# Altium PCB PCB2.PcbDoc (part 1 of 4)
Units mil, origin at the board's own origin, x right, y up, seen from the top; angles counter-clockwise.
Board outline 3980.79 x 2126 mil, 6 copper layers (Top Layer, Signal Layer 1, Signal Layer 2, Signal Layer 3, Signal Layer 4, Bottom Layer), stack 61.485 mil thick; 358 components, 190 nets, 1000 pads, 509 vias.
Unrouted connection lines stored in the file: 83.
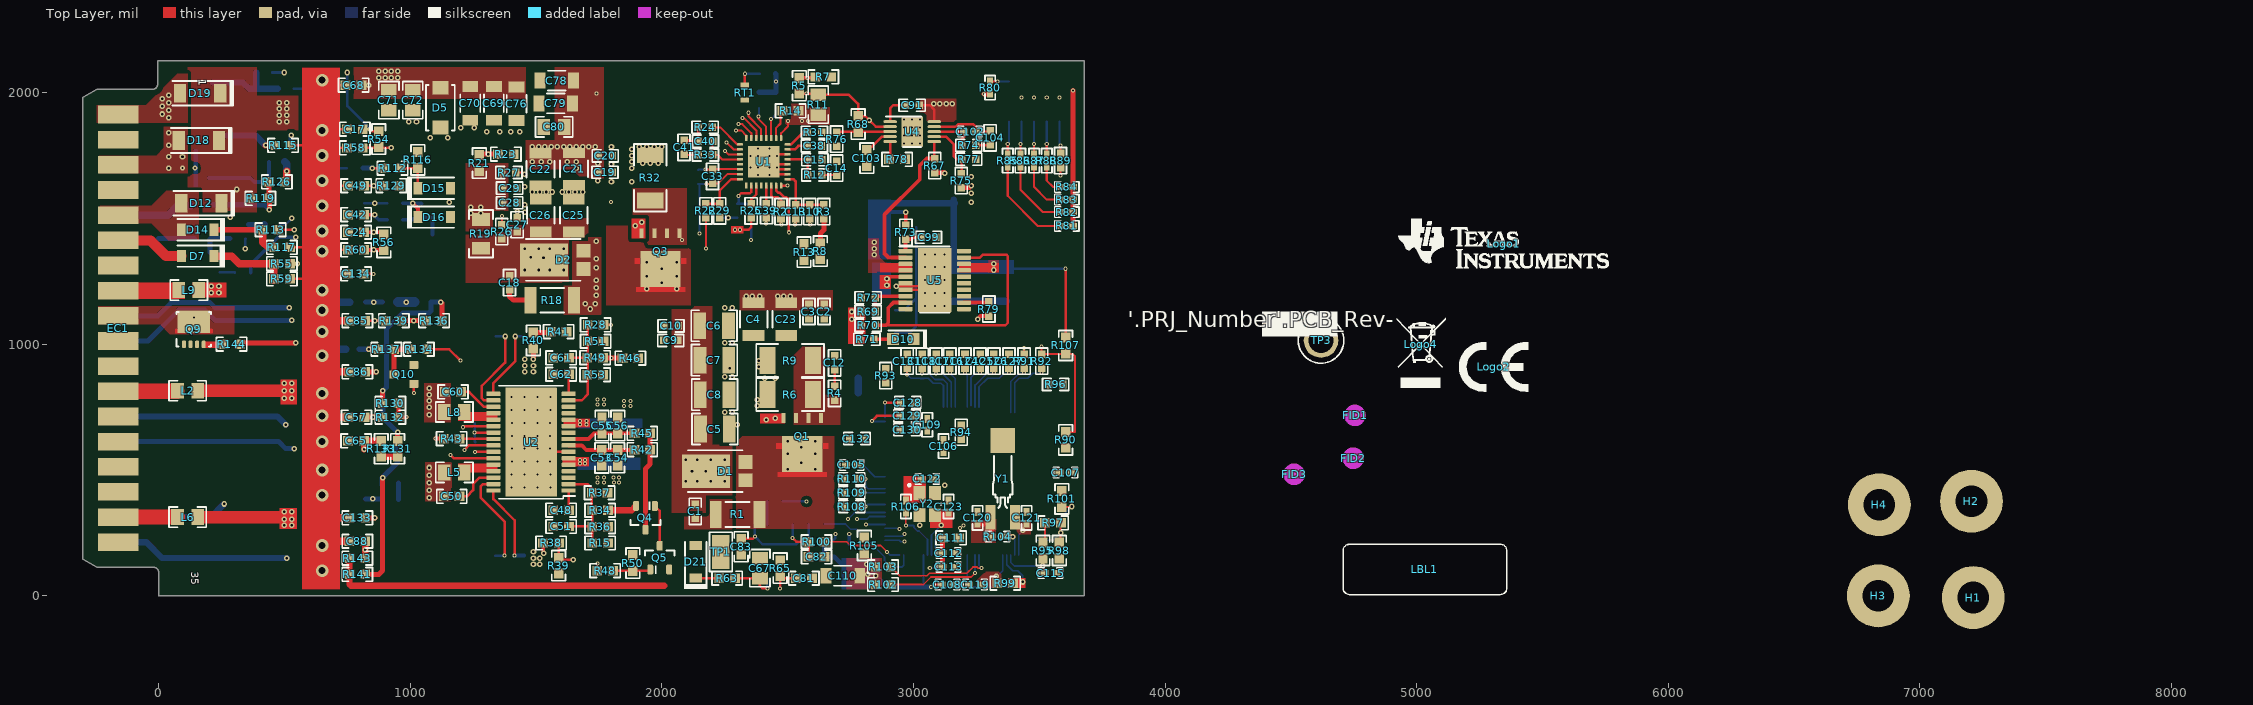
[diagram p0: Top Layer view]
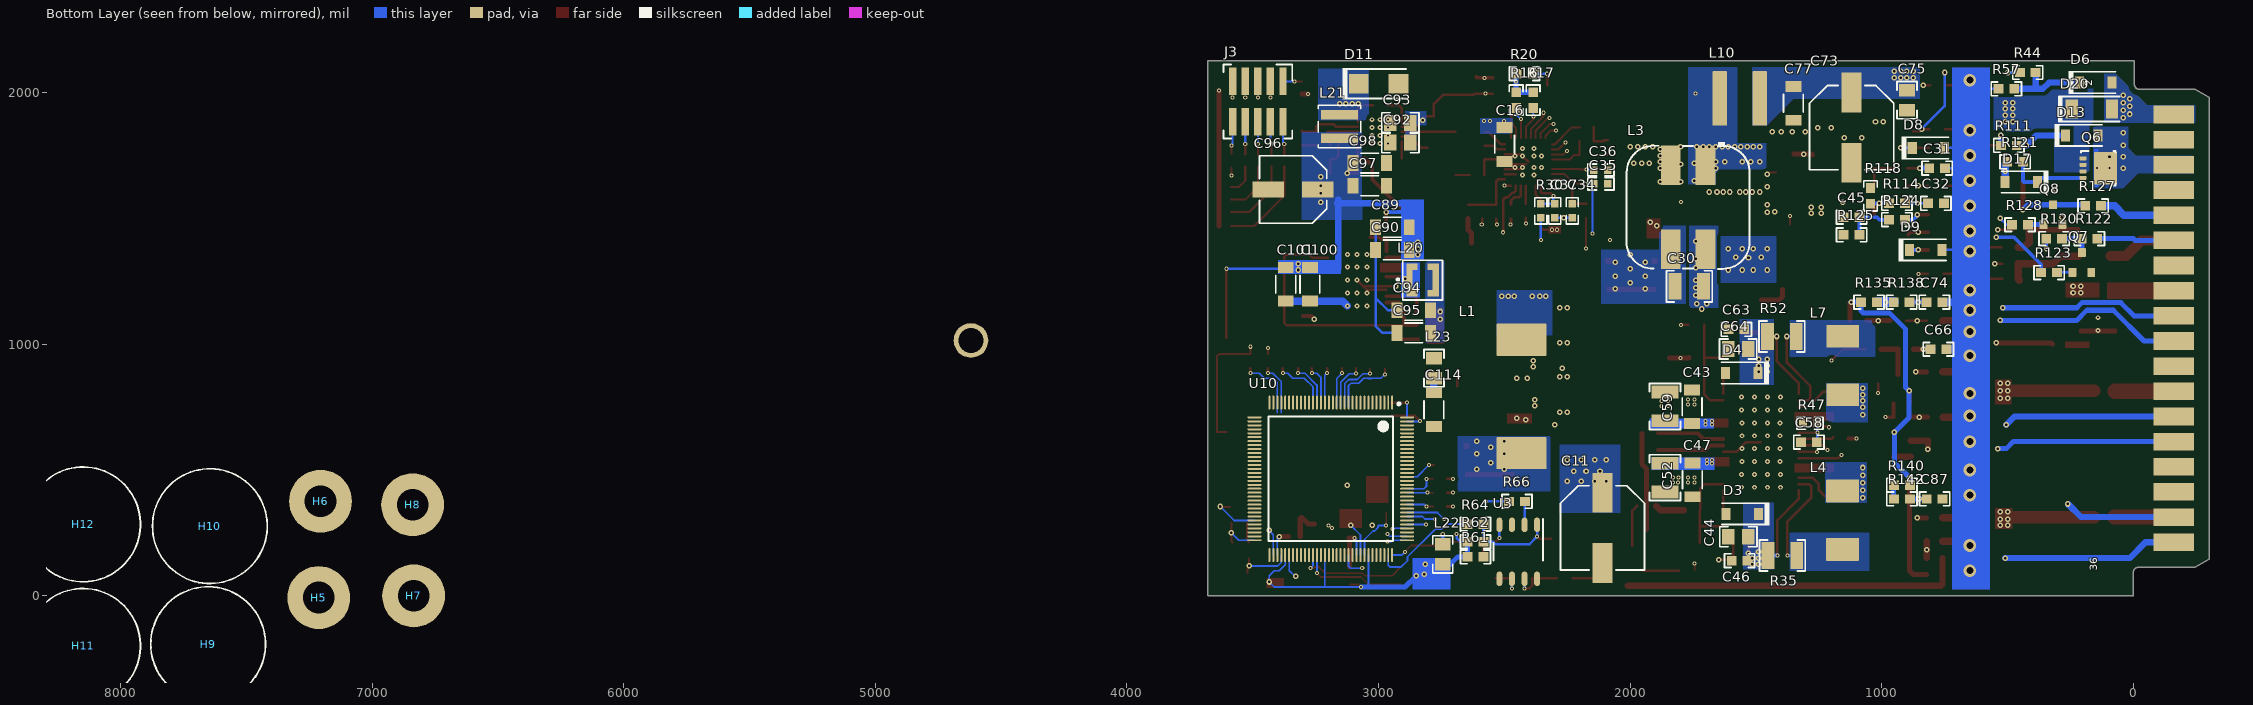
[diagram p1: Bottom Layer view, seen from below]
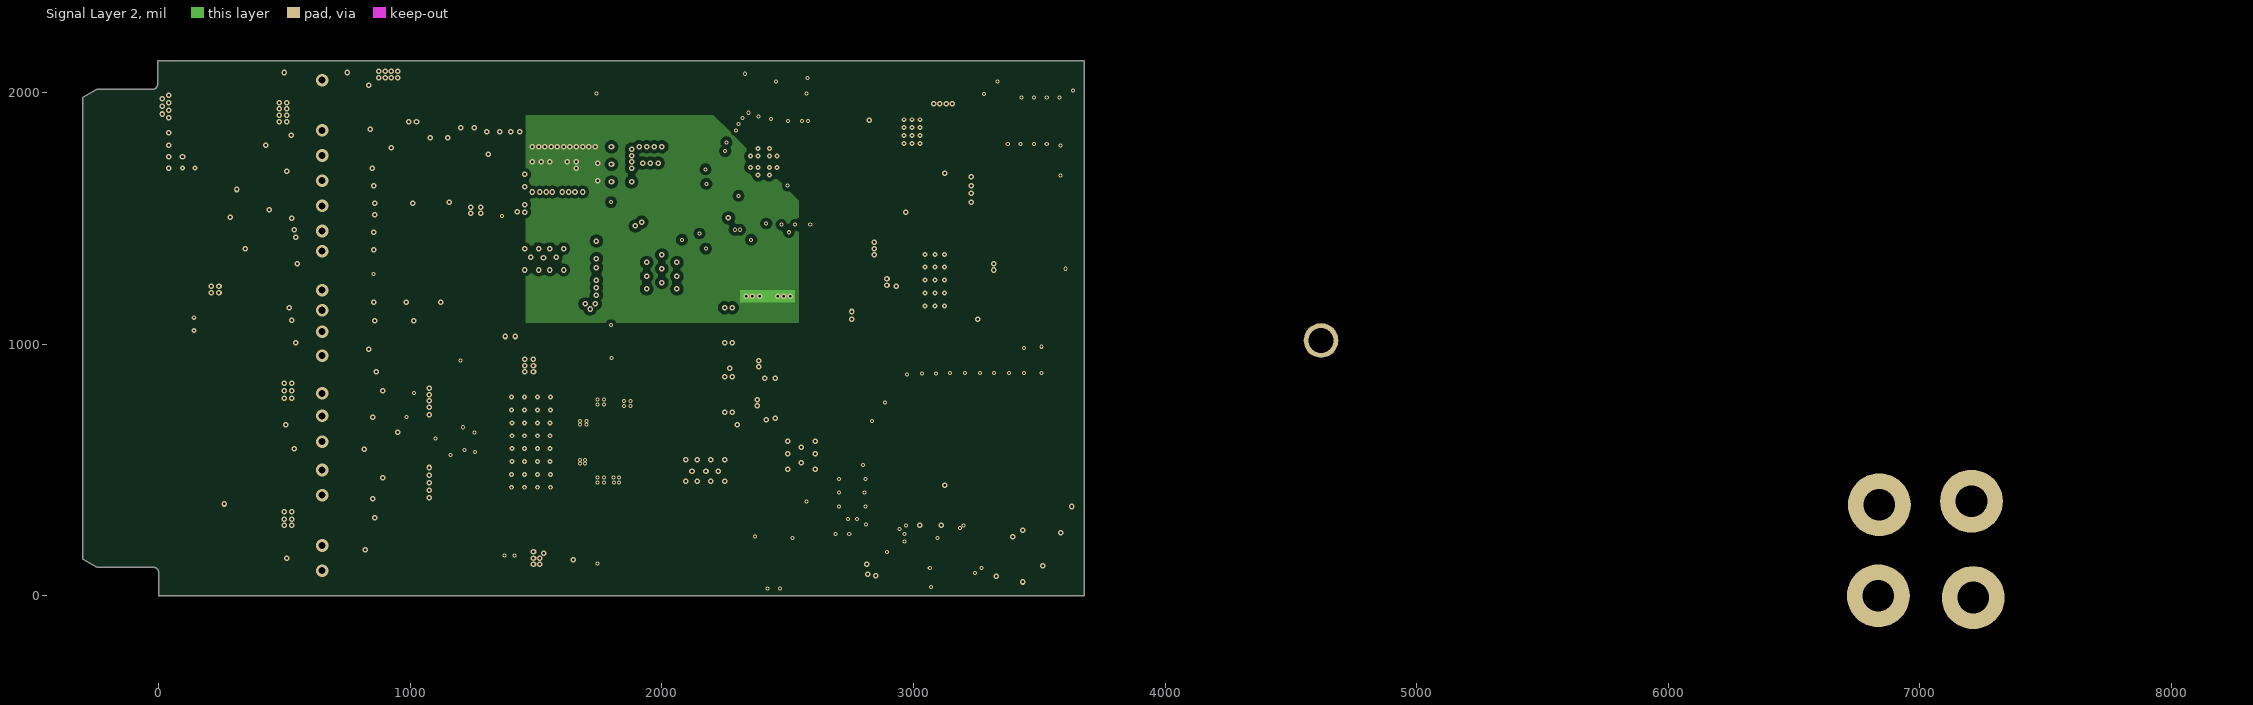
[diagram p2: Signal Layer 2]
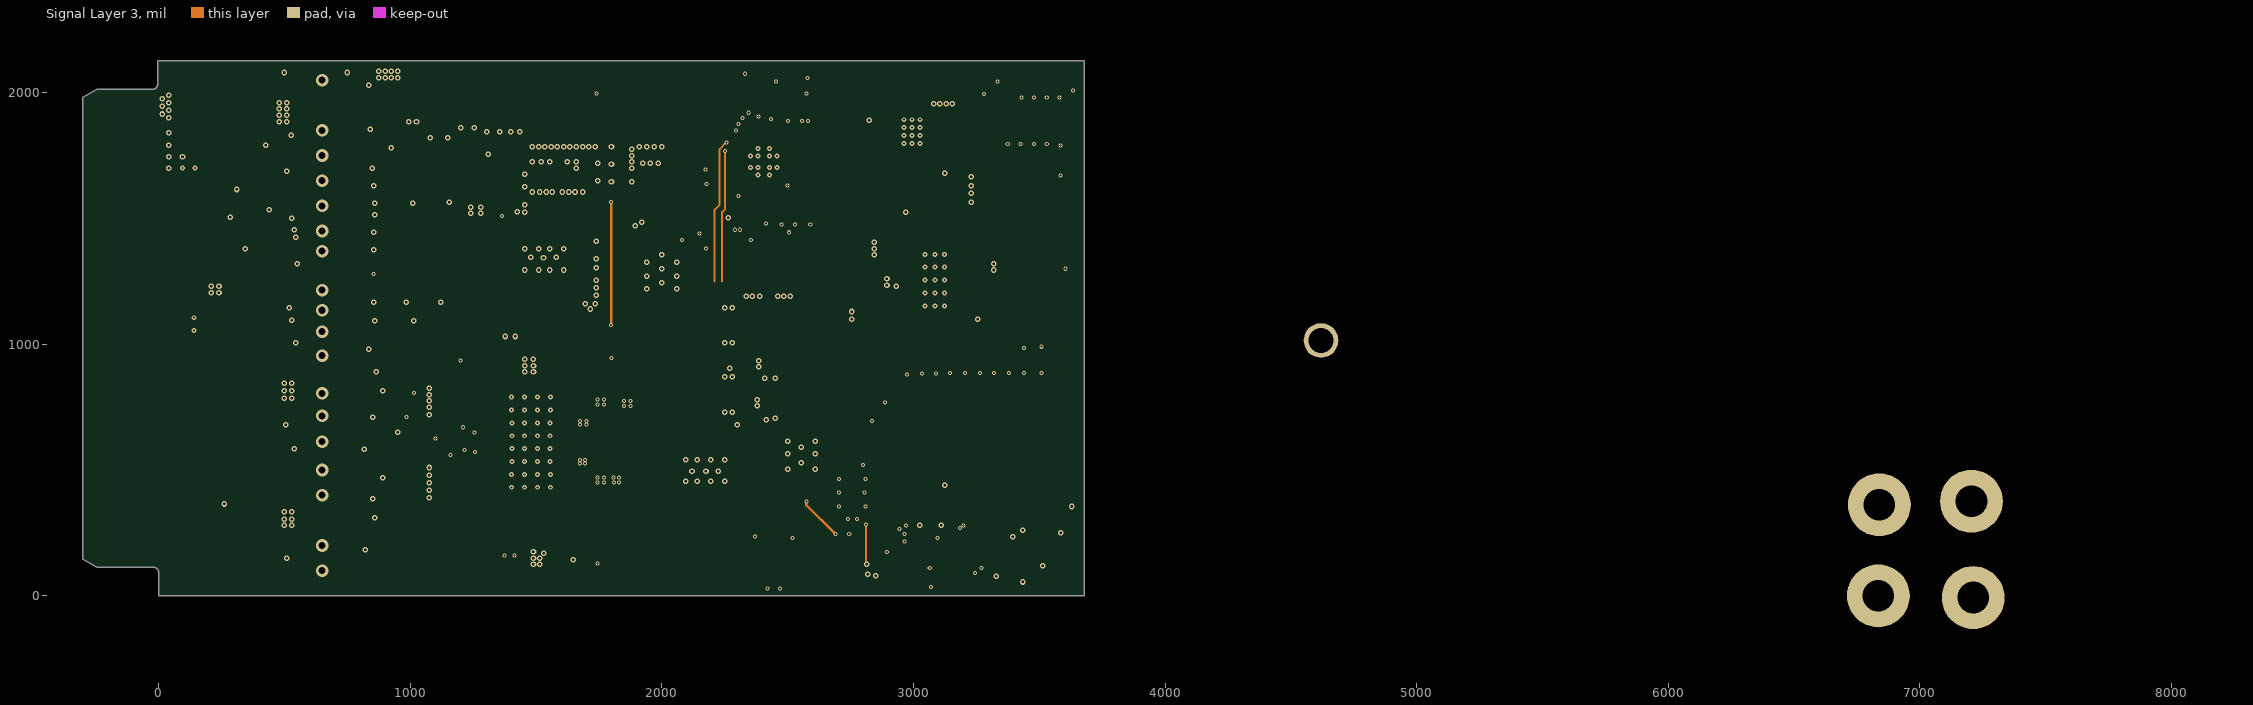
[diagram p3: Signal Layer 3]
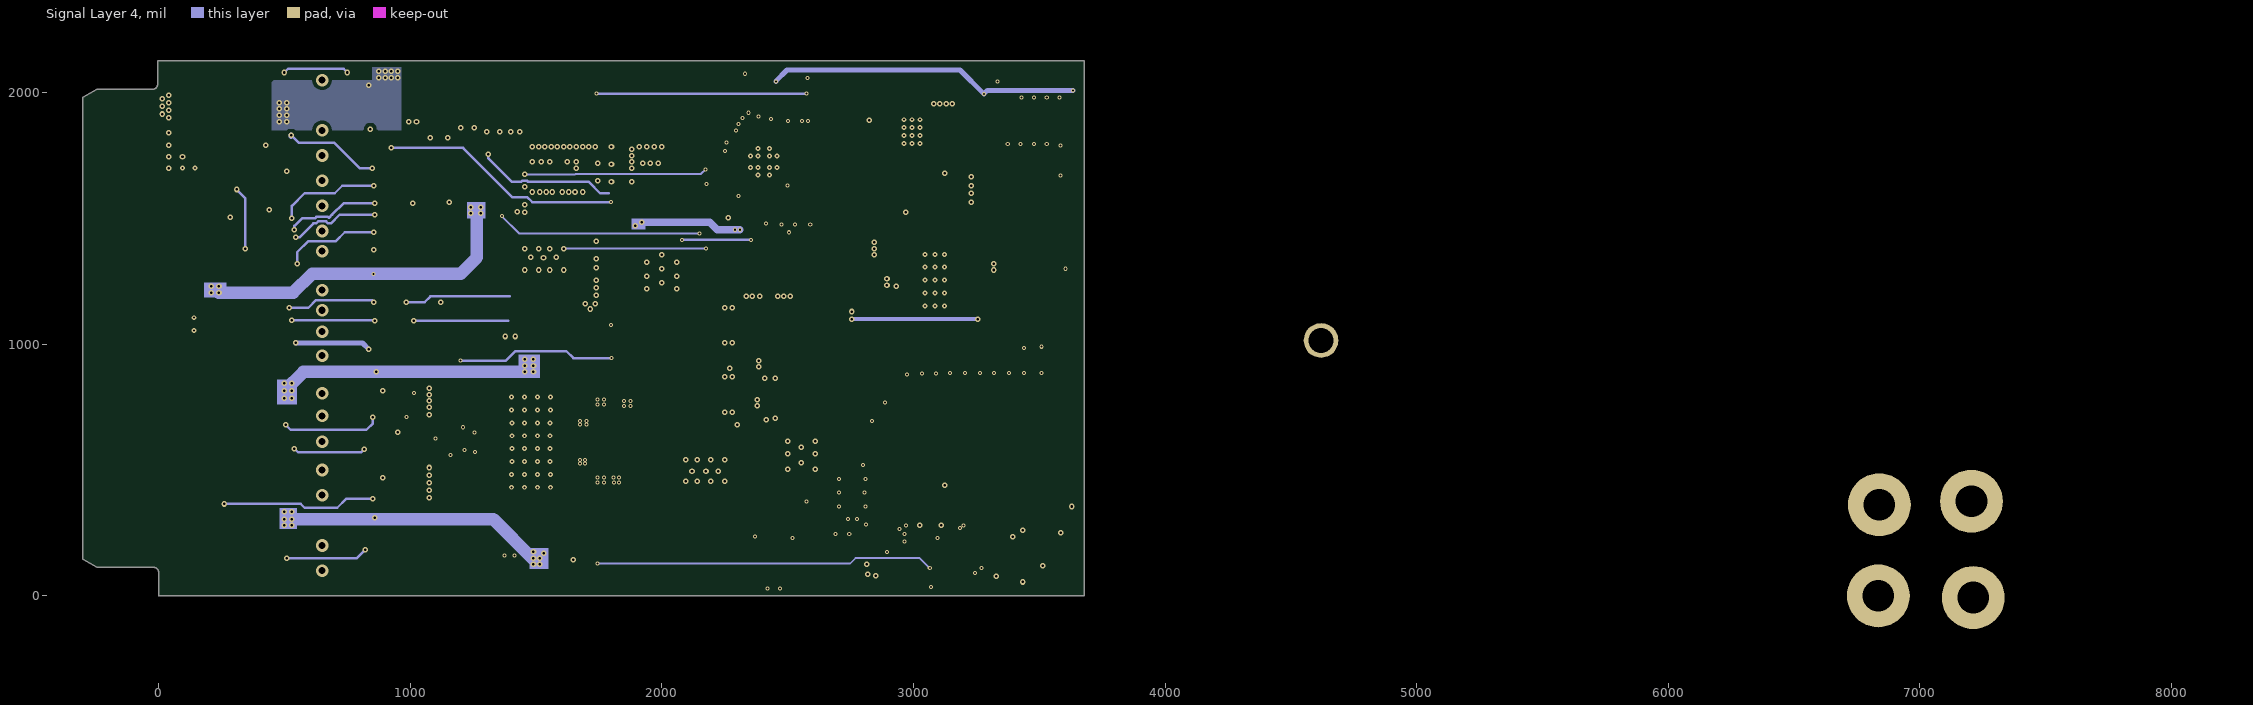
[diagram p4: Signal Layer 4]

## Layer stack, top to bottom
Top Solder: solder mask 0.4, Solder Resist, Dk 3.5
Top Layer: signal copper 1.417
Dielectric 1: core 12, FR-4, Dk 4.2
Signal Layer 1: signal copper 1.417
Dielectric 2: prepreg 8.5, FR-4, Dk 4.2
Signal Layer 2: signal copper 1.4
Dielectric 3: core 12, FR-4, Dk 4.2
Signal Layer 3: signal copper 1.417
Dielectric 4: prepreg 8.5, FR-4, Dk 4.2
Signal Layer 4: signal copper 1.417
Dielectric 5: core 12, Dk 4.2
Bottom Layer: signal copper 1.417
Bottom Solder: solder mask 0.4, Solder Resist, Dk 3.5

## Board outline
-300.79,144.88 -300.79,1981.17 -245.67,2012.99 -23.62,2012.99 ccw(c-23.62,2032.68) -3.94,2032.68 -3.94,2125.98 -3.93,2125.99 3680,2125.99 3680,-0.01 0.01,-0.01 0,0 0,93.31 ccw(c-19.69,93.31) -19.69,112.99 -245.67,112.99

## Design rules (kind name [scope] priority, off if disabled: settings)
AcuteAngle [All] p1: minimum=4.50000000000000E+0001 checktracksonly=FALSE
AssemblyTestPointUsage [All] p1: valid=2
BoardOutlineClearance BoardOutlineClearance_MountingHoles [OnCopper and InComponentClass('Mounting Holes')] p1: gap=40 ignorepadtopadclearanceinfootprint=FALSE
BoardOutlineClearance BoardOutlineClearance_Poly [OnCopper and IsPoly] p2: gap=25 ignorepadtopadclearanceinfootprint=FALSE
BoardOutlineClearance [OnCopper and Not InComponentClass('Logo') and not InComponentClass('FiducialMark') and not InRegion(1000,500,4000,800) and not InPoly] p3: gap=25 ignorepadtopadclearanceinfootprint=FALSE
Clearance Clearance_Keepouts [((IsTrack Or IsArc) And Not InPoly) And IsFree and IsKeepOut vs ((IsTrack Or IsArc) And Not InPoly) And IsFree and IsKeepOut] p1: gap=0 ignorepadtopadclearanceinfootprint=FALSE
Clearance Clearance_Poly [InPolygon] p2: gap=15 ignorepadtopadclearanceinfootprint=FALSE except(0: Arc-Hole Track-Hole SMDPad-Hole THPad-Hole Via-Hole Fill-Hole Poly-Hole Region-Hole Text-Hole)
Clearance Clearance_FiducialMark [IsKeepOut and InComponentClass('FiducialMark') vs IsPad and InComponentClass('FiducialMark')] p3: gap=0 ignorepadtopadclearanceinfootprint=FALSE
Clearance [All] p4: gap=7.87 ignorepadtopadclearanceinfootprint=FALSE except(0: Arc-Hole Track-Hole SMDPad-Hole THPad-Hole Via-Hole Fill-Hole Poly-Hole Region-Hole Text-Hole)
ComponentClearance ComponentClearance_MountingHoles_FiducialMarks [InComponentClass('Mounting Holes') vs InComponentClass('FiducialMark')] p1: gap=50 collisioncheckmode=3 verticalgap=10 showdistances=FALSE
ComponentClearance ComponentClearance_Shunt [InComponentClass('Header') vs InComponentClass('Shunt')] p2: gap=0 collisioncheckmode=3 verticalgap=0 showdistances=FALSE
ComponentClearance ComponentClearance_Logo [InComponentClass('Logo')] p3: gap=50 collisioncheckmode=3 verticalgap=10 showdistances=FALSE
ComponentClearance ComponentClearance_ScrewToNut [(HasFootprint('NY PMS 440 0025 PH')) vs (HasFootprint('Keystone_1902C'))] p4: gap=5 collisioncheckmode=3 verticalgap=10 showdistances=FALSE
ComponentClearance ComponentClearance_MountingHoles [InComponentClass('Mounting Holes')] p5: gap=100 collisioncheckmode=3 verticalgap=100000 showdistances=FALSE
ComponentClearance ComponentClearance_SmallPassives [HasFootprint('0201*') or HasFootprint('0402*') or HasFootprint('0508') or HasFootprint('0603*') or HasFootprint('0612') or HasFootprint('0805*') or HasFootprint('0815*') or HasFootprint('0830*') or HasFootprint('1206*') or HasFootprint('1210*') or HasFootprint('1808*') or HasFootprint('1812*') or HasFootprint('1825*') or HasFootprint('2010*') or HasFootprint('2220*') or HasFootprint('2225*') or HasFootprint('2512*') or HasFootprint('2728*') or HasFootprint('3518*') vs HasFootprint('0201*') or HasFootprint('0402*') or HasFootprint('0508') or HasFootprint('0603*') or HasFootprint('0612') or HasFootprint('0805*') or HasFootprint('0815*') or HasFootprint('0830*') or HasFootprint('1206*') or HasFootprint('1210*') or HasFootprint('1808*') or HasFootprint('1812*') or HasFootprint('1825*') or HasFootprint('2010*') or HasFootprint('2220*') or HasFootprint('2225*') or HasFootprint('2512*') or HasFootprint('2728*') or HasFootprint('3518*')] p6: gap=14.96 collisioncheckmode=3 verticalgap=10 showdistances=FALSE
ComponentClearance ComponentClearance_THtoSMT [IsThruComponent vs IsSMTComponent] p7: gap=40 collisioncheckmode=3 verticalgap=30 showdistances=FALSE
ComponentClearance ComponentClearance_THtoTH [IsThruComponent vs IsThruComponent] p8: gap=30 collisioncheckmode=3 verticalgap=30 showdistances=FALSE
ComponentClearance [All] p9: gap=20 collisioncheckmode=3 verticalgap=10 showdistances=FALSE
DiffPairsRouting [All] p1: maxlimit=100 minlimit=10 mostfreqgap=10 toplayer_minwidth=15 toplayer_maxwidth=15 toplayer_prefwidth=15 midlayer1_minwidth=15 midlayer1_maxwidth=15 midlayer1_prefwidth=15 midlayer2_minwidth=15 midlayer2_maxwidth=15 midlayer2_prefwidth=15 midlayer3_minwidth=15 midlayer3_maxwidth=15 midlayer3_prefwidth=15 midlayer4_minwidth=15 midlayer4_maxwidth=15 midlayer4_prefwidth=15 bottomlayer_minwidth=15 bottomlayer_maxwidth=15 bottomlayer_prefwidth=15 maxuncoupledlength=1000
FabricationTestPointUsage TestPointUsage [All] p1: valid=2 allowmultiple=FALSE
FabricationTestpoint Testpoint [All] p1: side=3 testpointundercomponent=TRUE minsize=40 maxsize=100 preferedsize=60 minholesize=0 maxholesize=40 preferedholesize=32 testpointgrid=1 allowsidetop=TRUE allowsidebottom=TRUE usegrid=TRUE gridtolerance=0.01
FanoutControl Fanout_LCC [IsLCC] p1: bgadir=Out bgaviamode=Centered fanoutstyle=Auto fanoutdirection=Alternating viagrid=1 // Fanout_LCC (Default Rule)
FanoutControl Fanout_BGA [IsBGA] p2: bgadir=Out bgaviamode=Centered fanoutstyle=Auto fanoutdirection=Alternating viagrid=1 // Fanout_BGA (Default Rule)
FanoutControl Fanout_Default [All] p4: bgadir=Out bgaviamode=Centered fanoutstyle=Auto fanoutdirection=Alternating viagrid=1 // Fanout_Default (Default Rule)
FanoutControl Fanout_Small [(CompPinCount < 5)] p5: bgadir=Out bgaviamode=Centered fanoutstyle=Auto fanoutdirection=OutThenIn viagrid=1 // Fanout_Small (Default Rule)
HoleSize [All] p1: absolutevalues=TRUE maxlimit=251 minlimit=7.87 maxpercent=80.000 minpercent=20.000
MinimumAnnularRing MinimumAnnularRing_ThermalPadVias [IsVia and InAnyComponent] p1: minimumring=5.91
MinimumAnnularRing [All] p2: minimumring=8
MinimumSolderMaskSliver MinimumSolderMaskSliver_Logo [InComponentClass('Logo') vs InComponentClass('Logo')] p1: minsoldermaskwidth=0.7
MinimumSolderMaskSliver [All] p2: minsoldermaskwidth=3.94
PlaneConnect [All] p1: planeconnectstyle=Relief reliefexpansion=10 reliefentries=4 reliefconductorwidth=10 reliefairgap=10
PolygonConnect [All] p1: connectstyle=Direct reliefconductorwidth=10 reliefentries=4 polygonreliefangle="90 Angle" airgapwidth=10
RoutingVias ThermalPadVias [IsVia and InAnyComponent] p1: holewidth=7.87 width=19.68 viastyle="Through Hole" minholewidth=7.87 minwidth=19.68 maxholewidth=12.99 maxwidth=23.62
RoutingVias [All] p2: holewidth=16 width=34 viastyle="Through Hole" minholewidth=7.87 minwidth=26 maxholewidth=40 maxwidth=65
SilkToBoardRegionClearance [Not ((IsComment or IsDesignator) And (Hide <> 'False')) and not InRegion(1000,500,4000,800)] p1:
SilkToSilkClearance SilkToSilkClearance_Pb-FreeLogo [(HasFootprint('Pb-Free_Overlay_Medium') OR HasFootprint('Pb-Free_Overlay_Small')) vs (HasFootprint('Pb-Free_Overlay_Medium') OR HasFootprint('Pb-Free_Overlay_Small'))] p1: silktosilkclearance=0
SilkToSilkClearance [All] p2: silktosilkclearance=4
SilkToSolderMaskClearance SilkToComponentPadClearance [(IsPad or IsFill or IsRegion) and InAnycomponent] p1: minsilkscreentomaskgap=5 clearancetoexposedcopper=TRUE
SilkToSolderMaskClearance "Silk to Solder Mask Opening" [All] p2: minsilkscreentomaskgap=4 clearancetoexposedcopper=FALSE
SolderMaskExpansion [All] p1: expansion=1.97
Width [All] p1: maxlimit=100 minlimit=6 preferedwidth=10 checkconnectedcopper=TRUE
15 further rules are at their usual default settings.

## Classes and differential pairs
component class "Mounting Holes": H1 H2 H3 H4
component class Logo: Logo1
component class EVM_Hardware: FID1 FID2 FID3 H1 H2 H3 H4 H5 H6 H7 H8 H9 H10 H11 H12 LBL1 Logo1 Logo2 Logo3 Logo4 ZZ1 ZZ2 ZZ3 ZZ4
component class FiducialMark: FID1 FID2 FID3
component class AssemblyNote: ZZ1 ZZ2 ZZ3 ZZ4
component class Label: LBL1
component class "BOOST- SEPIC": C1 C2 C3 C4 C5 C6 C7 C8 C9 C10 C11 C12 C13 C14 C15 C16 C18 C19 C20 C21 C22 C23 C25 C26 C27 C28 C29 C30 C33 C34 C35 C36 C37 C38 C39 C40 C41 D1 D2 L1 L3 Q1 Q3 R1 R2 R3 R4 R5 R6 R7 R8 R9 R10 R11 R12 R13 R14 R16 R17 R18 R19 R20 R21 R22 R23 R24 R25 R26 R27 R29 R30 R31 R32 R33 R90 R107 RT1 TP3 U1
component class Buck: C43 C44 C46 C47 C48 C50 C51 C52 C53 C54 C55 C56 C58 C59 C60 C61 C62 C63 C64 D3 D4 L4 L5 L7 L8 Q4 Q5 R15 R28 R34 R35 R36 R37 R38 R39 R40 R41 R42 R43 R45 R46 R47 R48 R49 R50 R51 R52 R53 U2
component class Header: J3
component class TIDA-0x_Battery: C17 C24 C31 C32 C42 C45 C49 C57 C65 C66 C68 C69 C70 C71 C72 C73 C74 C75 C76 C77 C78 C79 C80 C85 C86 C87 C88 C133 C134 C? D5 D6 D7 D8 D9 D12 D13 D14 D15 D16 D17 D18 D19 D20 D? EC1 L2 L6 L9 L10 Q6 Q7 Q8 Q9 Q10 Q? R44 R54 R55 R56 R57 R58 R59 R60 R111 R112 R113 R114 R115 R116 R117 R118 R119 R120 R121 R122 R123 R124 R125 R126 R127 R128 R129 R130 R131 R132 R133 R134 R135 R136 R137 R138 R139 R140 R141 R142 R143 R144 R?
component class TIDA-0x_MSP432E4x: C67 C81 C82 C83 C105 C106 C107 C108 C109 C110 C111 C112 C113 C114 C115 C116 C117 C118 C119 C120 C121 C122 C123 C124 C125 C126 C127 C128 C129 C130 C131 C132 C? D21 J3 L22 L23 R61 R62 R63 R64 R65 R66 R80 R81 R82 R83 R84 R85 R86 R87 R88 R89 R91 R92 R93 R94 R95 R96 R97 R98 R99 R100 R101 R102 R103 R104 R105 R106 R108 R109 R110 TP1 U3 U10 Y1 Y2
component class TIDA-0x_PwrSupplies: C89 C90 C91 C92 C93 C94 C95 C96 C97 C98 C99 C100 C101 C102 C103 C104 D10 D11 L20 L21 R67 R68 R69 R70 R71 R72 R73 R74 R75 R76 R77 R78 R79 U4 U5

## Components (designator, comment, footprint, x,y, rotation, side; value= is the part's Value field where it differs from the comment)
C1 "Capacitor" 0603_HV 2133,335.68 r90 top value=470pF
C2 "Capacitor" 0603_HV 2645,1130 r90 top value=0.01uF
C3 "Capacitor" 0603_HV 2585,1130 r90 top value=0.1uF
C4 "C3225X7R1H106M250AC" 1210_280 2365,1100 r270 top value=10uF
C5 "Capacitor" 1210_220 2210.91,662.68 r0 top value=4.7uF
C6 "Capacitor" 1210_220 2207.91,1073.68 r0 top value=4.7uF
C7 "Capacitor" 1210_220 2208.91,936.68 r0 top value=4.7uF
C8 "Capacitor" 1210_220 2209.97,799.68 r0 top value=4.7uF
C9 "Capacitor" 0603_HV 2035.61,1014.91 r180 top value=0.1uF
C10 "Capacitor" 0603_HV 2036.61,1072.91 r0 top value=0.01uF
C11 "EEE-FK1K330P" SM_RADIAL_F 2110,270 r270 bottom value=33uF
C12 "Capacitor" 0603_HV 2687,925.68 r270 top value=1000pF
C13 "Capacitor" 0603_HV 2531.76,1527.24 r90 top value=1000pF
C14 "GRM188R71E473KA01D" 0603_HV 2695,1700 r90 top value=0.047uF
C15 "885012006057" 0603_HV 2608.2,1732.94 r180 top value=100pF
C16 "Capacitor" 1206_180 2499.49,1793.9 r270 bottom value=1uF
C17 "GCM188R72A332KA37D" 0603 780,1855 r180 top value=3300pF
C18 "Capacitor" 0603_HV 1395,1245 r90 top value=470pF
C19 "Capacitor" 0603_HV 1774.15,1683.76 r180 top value=0.01uF
C20 "Capacitor" 0603_HV 1775.15,1748.76 r0 top value=0.1uF
C21 "C3225X7R1H106M250AC" 1210_280 1651.15,1696.76 r270 top value=10uF
C22 "C3225X7R1H106M250AC" 1210_280 1518.15,1694.76 r270 top value=10uF
C23 "C3225X7R1H106M250AC" 1210_280 2495,1100 r270 top value=10uF
C24 "GCM188R72A332KA37D" 0603 785,1445 r180 top value=3300pF
C25 "C3225X7R1H106M250AC" 1210_280 1650.15,1511.76 r90 top value=10uF
C26 "C3225X7R1H106M250AC" 1210_280 1519.15,1511.76 r90 top value=10uF
C27 "Capacitor" 0603_HV 1425,1475 r90 top value=0.1uF
C28 "Capacitor" 0603_HV 1395.2,1562.44 r0 top value=0.01uF
C29 "Capacitor" 0603_HV 1395.2,1620.44 r0 top value=0.01uF
C30 "Capacitor" 1210_220 1765,1230 r180 bottom value=4.7uF
C31 "GCM188R72A332KA37D" 0603 780,1700 r180 bottom value=3300pF
C32 "GCM188R72A332KA37D" 0603 785,1560 r180 bottom value=3300pF
C33 "Capacitor" 0603_HV 2201.85,1667.24 r90 top value=0.1uF
C34 "Capacitor" 0603_HV 2230,1530 r90 bottom value=1000pF
C35 "Capacitor" 0603_HV 2116.85,1637.24 r180 bottom value=0.01uF
C36 "Capacitor" 0603_HV 2116.85,1692.24 r180 bottom value=0.01uF
C37 "Capacitor" 0603_HV 2300,1530 r90 bottom value=1000pF
C38 "Capacitor" 0603_HV 2606.52,1787.94 r180 top value=2.2uF
C39 "Capacitor" 0603_HV 2416,1531 r90 top value=2.2uF
C40 "885012006057" 0603_HV 2173.5,1807.24 r180 top value=100pF
C41 "CGA3E3X7S2A104K080AB" 0603_HV 2088.5,1782.24 r90 top value=0.1uF
C42 "GCM188R72A332KA37D" 0603 785,1515 r180 top value=3300pF
C43 "CGA5L3X7S2A225M160AB" 1206_190 1754,751.77 r270 bottom value=2.2uF
C44 "CGA4F3X7S2A224M085AE" 0805_HV 1570,235 r0 bottom value=0.22uF
C45 "GCM188R72A332KA37D" 0603 1120,1505 r0 bottom value=3300pF
C46 "CGA3E3X7S2A104K080AB" 0603 1565,140 r0 bottom value=0.1uF
C47 "CGA5L3X7S2A225M160AB" 1206_190 1753,460.77 r270 bottom value=2.2uF
C48 "GRM188R71C222KA01D" 0603 1600.2,340.59 r180 top value=2200pF
C49 "GCM188R72A332KA37D" 0603 785,1630 r180 top value=3300pF
C50 "CGA3E2X7R1E104K080AA" 0603 1165.2,395.59 r0 top value=0.1uF
C51 "GRM188R72A102KA01D" 0603 1600.2,275.59 r180 top value=1000pF
C52 "CGA6M3X7R2A155K200AB" 1210_220 1862,469.77 r90 bottom value=1.5uF
C53 "GCM188R71C105KA64D" 0603 1761.56,548.59 r90 top value=1uF
C54 "CL10B104KO8WPNC" 0603 1824.37,548.77 r90 top value=0.1uF
C55 "GCM188R71C105KA64D" 0603 1762.37,676.77 r90 top value=1uF
C56 "CL10B104KO8WPNC" 0603 1825.37,676.77 r90 top value=0.1uF
C57 "GCM188R72A332KA37D" 0603 786.5,710 r180 top value=3300pF
C58 "CL10B104KO8WPNC" 0603 1290.2,610.59 r0 bottom value=0.1uF
C59 "CGA6M3X7R2A155K200AB" 1210_220 1862,752.77 r90 bottom value=1.5uF
C60 "CGA3E2X7R1E104K080AA" 0603 1170.2,810.59 r0 top value=0.1uF
C61 "GRM188R72A102KA01D" 0603 1600.2,945.59 r0 top value=1000pF
C62 "GRM188R71C222KA01D" 0603 1600.2,880.59 r180 top value=2200pF
C63 "CGA3E3X7S2A104K080AB" 0603 1578,1058.77 r180 bottom value=0.1uF
C64 "CGA4F3X7S2A224M085AE" 0805_HV 1571,980.77 r0 bottom value=0.22uF
C65 "GCM188R72A332KA37D" 0603 785,616.06 r180 top value=3300pF
C66 "GCM188R72A332KA37D" 0603 775,980 r180 bottom value=3300pF
C67 "C0805C104K5RACAUTO" 0805_HV 2390,110 r270 top value=0.1uF
C68 "GCM188R71H103KA37D" 0603 775,2030 r180 top value=0.01uF
C69 "C3216X7R1H475K160AC" 1206_180 1332.6,1956.99 r270 top value=4.7uF
C70 "C3216X7R1H475K160AC" 1206_180 1238.6,1956.99 r270 top value=4.7uF
C71 "C0805C104K5RACAUTO" 0805_HV 915,1970 r270 top value=0.1uF
C72 "C0805C104K5RACAUTO" 0805_HV 1010,1970 r270 top value=0.1uF
C73 "EEE-FK1H101P" SM_RADIAL_F 1120,1860.67 r270 bottom value=100uF
C74 "GCM188R72A332KA37D" 0603 791,1167.27 r180 bottom value=3300pF
C75 "C0805C104K5RACAUTO" 0805_HV 900,1970 r270 bottom value=0.1uF
C76 "C3216X7R1H475K160AC" 1206_180 1422.6,1955.99 r270 top value=4.7uF
C77 "C3216X7R1H475K160AC" 1206_180 1351.6,1956.99 r270 bottom value=4.7uF
C78 "C3216X7R1H475K160AC" 1206_180 1582.6,2047.99 r180 top value=4.7uF
C79 "C3216X7R1H475K160AC" 1206_180 1578.6,1956.99 r180 top value=4.7uF
C80 "C0805C104K5RACAUTO" 0805_HV 1571.6,1863.99 r180 top value=0.1uF
C81 "GCM1885C2A221JA16D" 0603 2565,70 r180 top value=220pF
C82 "GCM1885C2A150JA16D" 0603 2615,155 r0 top value=15pF
C83 "GCM1885C2A150JA16D" 0603 2315,195 r270 top value=15pF
C85 "GCM188R72A332KA37D" 0603 790,1093.7 r180 top value=3300pF
C86 "GRM188R72A103KA01D" 0603 790,890 r180 top value=0.01uF
C87 "GCM188R72A332KA37D" 0603 790,385 r180 bottom value=3300pF
C88 "GCM188R72A332KA37D" 0603 790,216.85 r180 top value=3300pF
C89 "Capacitor" 1206_180 2945,1465 r0 bottom value=10uF
C90 "Capacitor" 1206_180 2945,1375 r0 bottom value=10uF
C91 "Capacitor" 0603_HV 2995,1950 r0 top value=0.1uF
C92 "CGA4J3X7S2A105K125AB" 0805_HV 2913.61,1801.16 r0 bottom value=1uF
C93 "CGA4J2X7R2A104K125AA" 0805_HV 2913.61,1879.96 r0 bottom value=0.1uF
C94 "Capacitor" 1206_180 2860,1135 r0 bottom value=10uF
C95 "Capacitor" 1206_180 2860,1045 r0 bottom value=10uF
C96 "EEEFP1C101AP" SM_RADIAL_D 3340,1615 r0 bottom value=100uF
C97 "Capacitor" 1206_180 3035,1630 r180 bottom value=10uF
C98 "Capacitor" 1206_180 3035,1720 r180 bottom value=10uF
C99 "Capacitor" 0603_HV 3060,1425 r0 top value=1uF
C100 "Capacitor" 1206_180 3273.21,1238.32 r270 bottom value=10uF
C101 "Capacitor" 1206_180 3369.21,1238.32 r270 bottom value=10uF
C102 "GRM1555C2A5R0CA01D" 0402 3225,1845 r0 top value=5pF
C103 "CGA3E2X7R2A223K080AA" 0603 2815,1740 r270 top value=0.022uF
C104 "Capacitor" 0603_HV 3305,1820 r90 top value=3900pF
C105 "GRM155R71C104KA88D" 0402 2755,520 r180 top value=0.1uF
C106 "GRM155R71C104KA88D" 0402 3120,595 r270 top value=0.1uF
C107 "GRM155R71C104KA88D" 0402 3605,490 r0 top value=0.1uF
C108 "GRM155R71C104KA88D" 0402 3135,45 r0 top value=0.1uF
C109 "GRM155R71C104KA88D" 0402 3055,680 r270 top value=0.1uF
C110 "Capacitor" 1206_180 2720,80 r180 top value=10uF
C111 "GRM188R61C225KE15D" 0603 3150,230 r0 top value=2.2uF
C112 "GRM155R61A105KE15D" 0402 3140,170 r0 top value=1uF
C113 "GRM155R71C104KA88D" 0402 3140,115 r0 top value=0.1uF
C114 "Capacitor" 1206_180 2780,740 r270 bottom value=2.2uF
C115 "GRM155R71C104KA88D" 0402 3545,90 r0 top value=0.1uF
C116 "C0603C331K5RACTU" 0603_HV 3145,933 r90 top value=330pF
C117 "C0603C331K5RACTU" 0603_HV 3090,933 r90 top value=330pF
C118 "C0603C331K5RACTU" 0603_HV 3035,932.45 r90 top value=330pF
C119 "GRM155R71C104KA88D" 0402 3245,45 r180 top value=0.1uF
C120 "GRM1555C1H120JA01D" 0402 3255,310 r90 top value=12pF
C121 "GRM1555C1H120JA01D" 0402 3450,310 r90 top value=12pF
C122 "GRM1555C1H120JA01D" 0402 3055,465 r0 top value=12pF
C123 "GRM1555C1H120JA01D" 0402 3140,355 r90 top value=12pF
C124 "C0603C331K5RACTU" 0603_HV 3205,933 r90 top value=330pF
C125 "C0603C331K5RACTU" 0603_HV 3265,933 r90 top value=330pF
C126 "C0603C331K5RACTU" 0603_HV 3320,933 r90 top value=330pF
C127 "C0603C331K5RACTU" 0603_HV 3380,933 r90 top value=330pF
C128 "C0603C331K5RACTU" 0603_HV 2977.4,768.15 r0 top value=330pF
C129 "C0603C331K5RACTU" 0603_HV 2975,715 r0 top value=330pF
C130 "C0603C331K5RACTU" 0603_HV 2975,660 r0 top value=330pF
C131 "C0603C331K5RACTU" 0603_HV 2975,932.45 r90 top value=330pF
C132 "C0603C331K5RACTU" 0603_HV 2775,625 r180 top value=330pF
C133 "GRM188R72A103KA01D" 0603 790,310 r180 top value=0.01uF
C134 "GRM188R72A103KA01D" 0603 785,1280 r180 top value=0.01uF
D1 "PDS3100Q-13" POWERDI5 2254,495.68 r180 top value=100V
D2 "PDS3100Q-13" POWERDI5 1610,1335 r180 top value=100V
D3 "BAS16D-E3-08" SOD-123 1555,325.77 r0 bottom value=100V
D4 "BAS16D-E3-08" SOD-123 1557,885.77 r0 bottom value=100V
D5 "SZ1SMA28CAT3G" SMA_Bi 1120,1940 r90 top value=28V
D6 "1N4148WQ-7-F" SOD-123 150,2040 r180 bottom value=100V
D7 "1N4148WQ-7-F" SOD-123 155,1350 r180 top value=100V
D8 "MMSZ4683-E3-08" SOD-123 814.43,1780 r180 bottom value=3V
D9 "MMSZ4683-E3-08" SOD-123 825,1375 r180 bottom value=3V
D10 "LED" LG_R971_Green 2960,1020 r0 top value=Green
D11 "DIODE_SCHOTTKY" SMA 3000,2035 r180 bottom value=60V
D12 "FSV530AF" SMAF 170,1560 r180 top value=30V
D13 "1N4148WQ-7-F" SOD-123 205,1830 r180 bottom value=100V
D14 "1N4148WQ-7-F" SOD-123 155,1455 r180 top value=100V
D15 "MMSZ4683-E3-08" SOD-123 1095,1620 r0 top value=3V
D16 "MMSZ4683-E3-08" SOD-123 1095,1505 r0 top value=3V
D17 "MMSZ4697-HE3-08" SOD-123 445,1645 r0 bottom value=10V
D18 "FSV530AF" SMAF 160,1810 r180 top value=30V
D19 "FSV530AF" SMAF 165,1997.5 r180 top value=30V
D20 "FSV530AF" SMAF 164.99,1934.99 r180 bottom value=30V
D21 "MMSD4148T1G" SOD-123 2135,135 r90 top value=100V
EC1 "EDGE_CONN_EBC18DCWN-S371" Sullins_EDGE_CONN_EBC18DCWN-S371 -300.79,1062.99 r270 top locked
FID1 "Fiducial" Fiducial10-20 4755.21,716.99 r0 top
FID2 "Fiducial" Fiducial10-20 4748.21,546.99 r0 top
FID3 "Fiducial" Fiducial10-20 4513.21,482.99 r0 top
H1 "NY PMS 440 0025 PH" "NY PMS 440 0025 PH" 7212.21,-7.01 r0 top locked
H2 "NY PMS 440 0025 PH" "NY PMS 440 0025 PH" 7205.21,375.99 r0 top
H3 "NY PMS 440 0025 PH" "NY PMS 440 0025 PH" 6835.21,-0.01 r0 top locked
H4 "NY PMS 440 0025 PH" "NY PMS 440 0025 PH" 6839.21,361.99 r0 top locked
H5 "1902C" Keystone_1902C 7212.21,-7.01 r180 bottom locked
H6 "1902C" Keystone_1902C 7205.21,375.99 r180 bottom locked
H7 "1902C" Keystone_1902C 6835.21,-0.01 r180 bottom locked
H8 "1902C" Keystone_1902C 6839.21,361.99 r180 bottom locked
H9 "SJ-5303 (CLEAR)" Bumpon_SJ5003Transparent 7652.21,-192.01 r180 bottom
H10 "SJ-5303 (CLEAR)" Bumpon_SJ5003Transparent 7645.21,276.99 r180 bottom
H11 "SJ-5303 (CLEAR)" Bumpon_SJ5003Transparent 8149.21,-199.01 r180 bottom
H12 "SJ-5303 (CLEAR)" Bumpon_SJ5003Transparent 8149.21,283.99 r180 bottom
J3 "Header_5x2" Samtec_FTSH-105-01-x-DV 3480,1965 r270 bottom
L1 "SPM12565VT-220M-D" SPM12565VT 2432,792.68 r270 bottom value=22uH
L2 "742792012" 0805_HV 115,815 r180 top value="33 ohm"
L3 "MSD1278-333ML" MSD1278 1769.81,1544.27 r270 bottom value=33uH
L4 "SPM6545VT-680M-D" SPM6545VT 1156,300.77 r270 bottom value=68uH
L5 "742792012" 0805_HV 1175.2,490.59 r180 top value="33 ohm"
L6 "742792012" 0805_HV 115,312.99 r180 top value="33 ohm"
L7 "SPM6545VT-680M-D" SPM6545VT 1155.2,915.59 r90 bottom value=68uH
L8 "742792012" 0805_HV 1175.2,730.59 r180 top value="33 ohm"
L9 "742792012" 0805_HV 120,1215 r180 top value="33 ohm"
L10 "XAL6030-332MEB" XAL6030 1564.6,1976.99 r0 bottom value=3.3uH
L20 "LPS3010-222MLB" LPS3010 2825,1255 r180 bottom value=2.2uH
L21 "Inductor_Iron" XAL4040 3155,1865 r270 bottom value=15uH
L22 "Ferrite_Bead" 0805_HV 2745,165 r270 bottom value="220 ohm"
L23 "Ferrite_Bead" 0805_HV 2780,905 r270 bottom value="60 ohm"
LBL1 "THT-14-423-10" Label_650x200 5033.21,104.99 r0 top
Logo1 "Texas Instruments" TI_Stacked_Overlay_Small 5346.21,1399.99 r0 top
Logo2 "CE Mark" CE_Mark_5mm 5306.21,909.99 r0 top
Logo3 "FCC disclaimer" FCC_disclaimer 2066.21,3379.99 r0 top
Logo4 "WEEE logo" WEEE_Minimum 5016.21,999.99 r0 top
Q1 "SQJA90EP-T1_GE3" PowerPAK_SO-8L 2558,595.68 r270 top value=80V
Q3 "SQJA90EP-T1_GE3" PowerPAK_SO-8L 1995.15,1330.76 r270 top value=80V
Q4 "SI2323DS" SOT-23 1935,310 r270 top value=-20V
Q5 "MMBT3904LT1G" SOT-23 1991.7,151.7 r90 top value="40 V"
Q6 "SI7617DN-T1-GE3" PowerPAK_1212-8#1 140,1700 r180 bottom value=-30V
Q7 "BSS123-7-F" FP-BSS123-7-F_SOT23-MFG 205,1325 r90 bottom
Q8 "BSS123-7-F" FP-BSS123-7-F_SOT23-MFG 320,1515 r90 bottom
Q9 "SQS840EN-T1-GE3" PowerPAK_1212-8#2 140,1060 r90 top value=40V
Q10 "BSS123-7-F" FP-BSS123-7-F_SOT23-MFG 975,880 r180 top
R1 "Resistor" 2010L 2301,323.68 r0 top value=7.5
R2 "CRCW06030000Z0EA" 0603_HV 2473.73,1527.33 r270 top value=0
R3 "CRCW0603100KFKEA" 0603_HV 2643.76,1527.24 r270 top value=100k
R4 "Resistor" 0603_HV 2687,804.68 r270 top value=100
R5 "CRCW0603200KFKEA" 0603 2546.85,2027.24 r270 top value=200k
R6 "CSRN2010FK40L0" 2010 2510,800 r0 top value=0.04
R7 "RMCF0603FT10K0" 0603 2641.85,2062.24 r180 top value=10.0k
R8 "CRCW0603200KFKEA" 0603 2630,1370 r90 top value=200k
R9 "CSRN2010FK40L0" 2010 2510,935 r0 top value=0.04
R10 "CRCW06034K12FKEA" 0603_HV 2587.76,1527.24 r90 top value=4.12k
R11 "Resistor" 0805_HV 2621.85,1952.24 r270 top value=1.00
R12 "ERJ-3EKF1472V" 0603_HV 2608.2,1672.94 r0 top value=14.7k
R13 "RMCF0603FT10K0" 0603 2565.22,1366.32 r90 top value=10.0k
R14 "CRCW06030000Z0EA" 0603 2511.85,1927.24 r0 top value=0
R15 "CRCW060310M0FKEA" 0603 1755,210 r180 top value=10.0Meg
R16 "RMCF0603FT10K0" 0603 2453,1970 r90 bottom value=10.0k
R17 "RMCF0603FT10K0" 0603 2386,1970 r90 bottom value=10.0k
R18 "Resistor" 2010L 1565,1175 r0 top value=7.5
R19 "PT1206FR-070R165L" 1206 1281.15,1438.76 r90 top value=0.165
R20 "RMCF0603FT10K0" 0603 2420,2075 r0 bottom value=10.0k
R21 "CRCW0603200KFKEA" 0603 1275,1720 r270 top value=200k
R22 "CRCW0603402KFKEA" 0603_HV 2175,1530 r270 top value=402k
R23 "CRCW060310K0FKEA" 0603 1380.1,1755.76 r180 top value=10.0k
R24 "Resistor" 0603_HV 2172.08,1862.24 r0 top value=100k
R25 "CRCW06030000Z0EA" 0603_HV 2355,1530 r270 top value=0
R26 "Resistor" 0603_HV 1364.15,1447.76 r270 top value=10.0
R27 "Resistor" 0603_HV 1392.2,1682.44 r180 top value=10.0
R28 "CRCW060310M0FKEA" 0603 1737,1076.77 r180 top value=10.0Meg
R29 "CRCW06039K09FKEA" 0603_HV 2230,1530 r90 top value=9.09k
R30 "Resistor" 0603_HV 2355,1530 r270 bottom value=100
R31 "CRCW0603130KFKEA" 0603_HV 2606.85,1842.24 r180 top value=130k
R32 "CSRN2010FK40L0" 2010 1954.15,1661.76 r270 top value=0.04
R33 "CRCW060347R5FKEA" 0603_HV 2173.5,1752.24 r0 top value=47.5
R34 "CRCW060315K8FKEA" 0603 1755,340 r0 top value=15.8k
R35 "ERJ-L14KF10CU" 1210 1395,160 r0 bottom value=0.1
R36 "CRCW06031K00FKEA" 0603 1755,275 r180 top value=1.00k
R37 "CRCW060330K1FKEA" 0603 1753,409.61 r180 top value=30.1k
R38 "CRCW0603200KFKEA" 0603 1560,210 r180 top value=200k
R39 "CRCW060310K0FKEA" 0603 1590,120 r90 top value=10.0k
R40 "CRCW0603200KFKEA" 0603 1489.52,1015 r270 top value=200k
R41 "CRCW060310K0FKEA" 0603 1590,1050 r180 top value=10.0k
R42 "ERJ-3GEY0R00V" 0603 1922.37,580.77 r180 top value=0
R43 "CRCW06031K00FKEA" 0603 1165,625 r180 top value=1.00k
R44 "CRCW060310K0FKEA" 0603 420,2080 r0 bottom value=10.0k
R45 "ERJ-3GEY0R00V" 0603 1922.37,645.77 r180 top value=0
R46 "RMCF0603FT10K0" 0603 1875,945 r180 top value=10.0k
R47 "Resistor" 0603_HV 1285.2,685.59 r180 bottom value=100k
R48 "RMCF0603FT10K0" 0603 1775,100 r180 top value=10.0k
R49 "CRCW060315K8FKEA" 0603 1735,946.77 r0 top value=15.8k
R50 "RMCF0603FT10K0" 0603 1885,130 r270 top value=10.0k
R51 "CRCW06031K00FKEA" 0603 1737,1011.77 r180 top value=1.00k
R52 "ERJ-L14KF10CU" 1210 1397,1030.77 r180 bottom value=0.1
R53 "CRCW060330K1FKEA" 0603 1735,878.77 r180 top value=30.1k
R54 "CRCW060310K0FKEA" 0603 875,1815 r270 top value=10.0k
R55 "CRCW060310K0FKEA" 0603 490,1320 r0 top value=10.0k
R56 "CRCW060310K0FKEA" 0603 895,1405 r270 top value=10.0k
R57 "CRCW060310K0FKEA" 0603 505,2015 r180 bottom value=10.0k
R58 "CRCW0603100KFKEA" 0603 780,1780 r0 top value=100k
R59 "CRCW060310K0FKEA" 0603 490,1260 r180 top value=10.0k
R60 "CRCW0603100KFKEA" 0603 785,1375 r0 top value=100k
R61 "CRCW060310K0FKEA" 0603 2615,155 r0 bottom value=10.0k
R62 "CRCW060310K0FKEA" 0603 2615,215 r0 bottom value=10.0k
R63 "CRCW060310R0FKEA" 0603 2260,70 r0 top value=10.0
R64 "CRCW060310R0FKEA" 0603 2615,285 r180 bottom value=10.0
R65 "CRCW060310R0FKEA" 0603 2470,110 r90 top value=10.0
R66 "CRCW060310K0FKEA" 0603 2450,375 r180 bottom value=10.0k
R67 "Resistor" 0603_HV 3085,1710 r270 top value=47.0k
R68 "ERJ-3EKF4023V" 0603 2780,1875 r90 top value=402k
R69 "Resistor" 0603_HV 2820,1130 r0 top value=31.6k
R70 "Resistor" 0603_HV 2820,1075 r180 top value=47.0k
R71 "Resistor" 0603_HV 2815,1020 r180 top value=680
R72 "Resistor" 0603_HV 2820,1185 r0 top value=10.0k
R73 "Resistor" 0603_HV 2970,1445 r270 top value=4.7
R74 "Resistor" 0603_HV 3220,1790 r180 top value=133k
R75 "Resistor" 0603_HV 3190,1650 r270 top value=52.3k
R76 "Resistor" 0603_HV 2695,1815 r90 top value=95.3k
R77 "Resistor" 0603_HV 3220,1735 r180 top value=10.0k
R78 "CRCW060371K5FKEA" 0603 2935,1735 r180 top value=71.5k
R79 "Resistor" 0603_HV 3300,1140 r270 top value=47.0k
R80 "RMCF0402JT100R" 0402 3305,2020 r270 top value=100
R81 "RMCF0402FT10K0" 0402 3610,1470 r0 top value=10.0k
R82 "RMCF0402FT10K0" 0402 3610,1525 r0 top value=10.0k
R83 "RMCF0402FT10K0" 0402 3610,1575 r0 top value=10.0k
R84 "RMCF0402FT10K0" 0402 3610,1625 r0 top value=10.0k
R85 "RMCF0402FT33R0" 0402 3375,1730 r270 top value=33.0
R86 "RMCF0402FT33R0" 0402 3425,1730 r270 top value=33.0
R87 "RMCF0402FT33R0" 0402 3480,1730 r270 top value=33.0
R88 "RMCF0402FT33R0" 0402 3530,1730 r270 top value=33.0
R89 "Resistor" 0603_HV 3585,1730 r270 top value=0
R90 "CRCW060310M0FKEA" 0603 3605,620 r90 top value=10.0Meg
R91 "Resistor" 0603_HV 3440,933 r90 top value=0
R92 "Resistor" 0603_HV 3510,933 r90 top value=0
R93 "Resistor" 0603_HV 2890,875 r90 top value=2.20k
R94 "Resistor" 0603_HV 3190,650 r90 top value=0
R95 "RC0603FR-0751RL" 0603 3515,180 r270 top value=51.0
R96 "Resistor" 0603_HV 3565,840 r0 top value=0
R97 "CRCW06031M00FKEA" 0603 3555,290 r180 top value=1.00Meg
R98 "RC0603FR-0710ML" 0603 3580,180 r270 top value=10.0Meg
R99 "RMCF0603FT10K0" 0603 3365,50 r180 top value=10.0k
R100 "CRCW060310R0FKEA" 0603 2615,215 r180 top value=10.0
R101 "CRCW06034K87FKEA" 0603 3590,385 r90 top value=4.87k
R102 "RMCF0603FT10K0" 0603 2880,45 r180 top value=10.0k
R103 "RMCF0603FT10K0" 0603 2880,115 r180 top value=10.0k
R104 "RC0402JR-070RL" 0402 3335,235 r180 top value=0
R105 "RMCF0603FT10K0" 0603 2805,200 r270 top value=10.0k
R106 "CRCW04022K00JNED" 0402 2970,355 r90 top value=2.0k
R107 "CRCW060310M0FKEA" 0603 3605,995 r270 top value=10.0Meg
R108 "CRCW06031K00FKEA" 0603_HV 2755,355 r180 top value=1.00k
R109 "CRCW06031K00FKEA" 0603_HV 2755,410 r0 top value=1.00k
R110 "CRCW06031K00FKEA" 0603_HV 2755,465 r0 top value=1.00k
R111 "CRCW060310K0FKEA" 0603 495,1790 r0 bottom value=10.0k
R112 "CRCW060310K0FKEA" 0603 930,1700 r0 top value=10.0k
R113 "CRCW060310K0FKEA" 0603 445.57,1455 r0 top value=10.0k
R114 "CRCW060310K0FKEA" 0603 940,1560 r0 bottom value=10.0k
R115 "CRCW060310K0FKEA" 0603 495,1790 r180 top value=10.0k
R116 "CRCW0603100KFKEA" 0603 1030.22,1732.45 r270 top value=100k
R117 "CRCW060310K0FKEA" 0603 490,1385 r180 top value=10.0k
R118 "CRCW0603100KFKEA" 0603 1045,1590 r270 bottom value=100k
R119 "RC0603FR-0710ML" 0603 405,1580 r180 top value=10.0Meg
R120 "CRCW060310K0FKEA" 0603 315,1420 r0 bottom value=10.0k
R121 "CRCW0603100KFKEA" 0603 470,1725 r180 bottom value=100k
R122 "CRCW06031K00FKEA" 0603 175,1420 r0 bottom value=1.00k
R123 "CRCW060310K0FKEA" 0603 335,1285 r0 bottom value=10.0k
R124 "CRCW060310K0FKEA" 0603 940,1495 r0 bottom value=10.0k
R125 "CRCW060310K0FKEA" 0603 1120,1435 r0 bottom value=10.0k
R126 "CRCW060310K0FKEA" 0603 470,1645 r0 top value=10.0k
R127 "CRCW06031K00FKEA" 0603 160,1550 r0 bottom value=1.00k
R128 "CRCW060310K0FKEA" 0603 450.57,1475 r0 bottom value=10.0k
R129 "CRCW060310K0FKEA" 0603 925,1630 r0 top value=10.0k
R130 "CRCW060310K0FKEA" 0603 921.5,765 r180 top value=10.0k
R131 "CRCW060310K0FKEA" 0603 950,584.45 r90 top value=10.0k
R132 "CRCW06031K00FKEA" 0603 921.5,710 r0 top value=1.00k
R133 "CRCW06031K00FKEA" 0603 885,584.45 r270 top value=1.00k
R134 "CRCW06031K00FKEA" 0603 1035,980 r0 top value=1.00k
R135 "CRCW060310K0FKEA" 0603 1051,1167.27 r0 bottom value=10.0k
R136 "CRCW060310K0FKEA" 0603 1095,1093.7 r0 top value=10.0k
R137 "CRCW06031K00FKEA" 0603 905,980 r0 top value=1.00k
R138 "CRCW06031K00FKEA" 0603 921,1167.27 r0 bottom value=1.00k
R139 "CRCW06031K00FKEA" 0603 935,1093.7 r0 top value=1.00k
R140 "CRCW060310K0FKEA" 0603 920,440 r180 bottom value=10.0k
R141 "CRCW060310K0FKEA" 0603 790,85 r0 top value=10.0k
R142 "CRCW06031K00FKEA" 0603 920,385 r0 bottom value=1.00k
R143 "CRCW06031K00FKEA" 0603 790,150 r180 top value=1.00k
R144 "CRCW060310R0FKEA" 0603 290,1000 r0 top value=10.0
RT1 "NCP18WF104J03RB" 0603S 2330,2000 r90 top value=100k
TP1 "5015" Testpoint_Keystone_Miniature 2234.18,174.71 r90 top
TP3 "GND" Keystone1502-2 4620.21,1014.99 r0 top
U1 "TPS92682QRHMQ1" RHM0032C 2405,1725 r270 top
U2 "TPS92520QDAPRQ1" DAP0032A_N 1480.2,610.59 r180 top
U3 "TLIN1029DRQ1" D0008A_N 2445,175 r270 bottom
U4 "TPS57060" DGQ0010D_N 2995,1845 r0 top
U5 "LM26420XMHX" PWP0020A_N 3085,1255 r0 top
U10 "MSP432E401YTPDT" PDT0128A 3190,465 r270 bottom
Y1 "CMR200T-32.768KDZY-UT" CFM_CMR200T 3355,445 r270 top
Y2 "NX3225GA-25.000M-STD-CRG-2" NDK_NX3225GA 3055,365 r0 top
ZZ1 "This Assembly Note is for PCB labels only" AssemblyNoteLabel -98.79,3937.99 r0 top
ZZ2 "These assemblies are ESD sensitive, ESD precautions shall be observed." AssemblyNote -98.79,3829.11 r0 top
ZZ3 "These assemblies must be clean and free from flux and all contaminants. Use of no clean flux is not acceptable." AssemblyNote -98.79,3740.55 r0 top
ZZ4 "These assemblies must comply with workmanship standards IPC-A-610 Class 2, unless otherwise specified." AssemblyNote -98.79,3651.99 r0 top

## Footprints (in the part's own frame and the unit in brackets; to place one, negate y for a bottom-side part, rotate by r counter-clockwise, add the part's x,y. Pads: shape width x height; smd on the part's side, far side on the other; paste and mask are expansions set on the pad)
0402 [mm] "0402 from SM-752 data"
  rect 0.8x0.6 smd: 1(-0.6,0) 2(0.6,0)
  silkscreen extent -1.22,-0.52 1.22,0.52, body extent -0.55,-0.3 0.55,0.3, height 0.6
0603 [mm] "0603 from SM-752 data"
  rect 1x0.95 smd: 1(-0.8,0) 2(0.8,0)
  silkscreen extent -1.52,-0.69 1.52,0.69, body extent -0.87,-0.47 0.87,0.47, height 1
0603_HV [mil] "Ernesto recommended land pattern.  26 mil between pads."
  rect 30x30 smd: 1(-28,0) 2(28,0)
  silkscreen extent -52,-24 52,24, body extent -34,-19 34,19, height 39
0603S [mil]
  rect 20x35 smd: 1(-30,0) 2(30,0)
  body extent -34,-19 34,19, height 39
0805_HV [mil] "0805 with 30mil clearance between pads"
  rect 50x63 smd: 1(-40,0) 2(40,0)
  silkscreen extent -74,-40 74,40, body extent -43,-29 43,29, height 57
1206 [mm] "1206 from SM-752 data"
  rect 1.3x1.85 smd: 1(-1.45,0) 2(1.45,0)
  silkscreen extent -2.4,-1.21 2.4,1.21, body extent -1.7,-0.9 1.7,0.9, height 1.35
1206_180 [mm] "1206_180"
  rect 1.1x1.6 smd: 1(-1.7,0) 2(1.7,0)
  silkscreen extent -0.9,-1 0.9,1, body extent -1.75,-0.95 1.75,0.95, height 1.8
1206_190 [mm] "1206_190"
  rect 1.1x1.6 smd: 1(-1.7,0) 2(1.7,0)
  silkscreen extent -0.9,-1 0.9,1, body extent -1.75,-0.95 1.75,0.95, height 1.9
1210 [mm] "1210 from SM-752 data"
  rect 1.3x2.7 smd: 1(-1.45,0) 2(1.45,0)
  silkscreen extent -2.32,-1.57 2.32,1.57, body extent -1.7,-1.35 1.7,1.35, height 1.35
1210_220 [mm] "1210"
  rect 1.3x2.7 smd: 1(-1.45,0) 2(1.45,0)
  silkscreen extent -2.32,-1.57 2.32,1.57, body extent -1.7,-1.35 1.7,1.35, height 2.2
1210_280 [mm] "SMD, 2-Leads, Body 3.6x2.8mm, Height 2.8mm"
  rect 1.1x2.2 smd: 1(-1.65,0) 2(1.65,0)
  silkscreen extent -0.84,-1.4 0.84,1.4, body extent -1.8,-1.4 1.8,1.4, height 2.8
2010 [mm] "Chip Capacitor, Body 5.08x2.54mm, IPC Medium Density"
  rect 1.6x2.7 smd: 1(-2.3,0) 2(2.3,0)
  silkscreen extent -3.42,-1.65 3.42,1.65, body extent -2.73,-1.45 2.73,1.45, height 1.66
2010L [mm]
  rect 1.2x2.7 smd: 1(-2.2,0) 2(2.2,0)
  silkscreen extent -1.2,-1.25 1.2,1.25, body extent -2.73,-1.45 2.73,1.45, height 1.66
AssemblyNote [mil] "Assembly Note"
AssemblyNoteLabel [mil] "Assembly Note for PCB Labels"
Bumpon_SJ5003Transparent [mil] "3M Hemispherical Bumpon transparent"
  round 1 on Mech4: 0(0,0)
  silkscreen extent -228,-228 228,228, body extent -219,-219 219,219, height 197
CE_Mark_5mm [mil] "Minimum text height for CE Mark"
  silkscreen extent -138,-98 138,98
CFM_CMR200T [mm] "SMD, 3-Leads, Dia 1.9mm"
  rect 2.5x1 smd: 1(3.375,1.25) 2(3.375,-1.25)
  rect 2.5x2.5 smd: 3(-4.375,0)
  silkscreen extent -2.8,-1 2.42,1, body extent -4.62,-1.42 4.38,1.42, height 2
D0008A_N [mm] "SOIC, 8-Leads, Body 4.9x3.9mm, Pitch 1.27mm, IPC Medium Density"
  oval 1.45x0.6 smd: 1(-2.725,1.905) 2(-2.725,0.635) 3(-2.725,-0.635) 4(-2.725,-1.905) 5(2.725,-1.905) 6(2.725,-0.635) 7(2.725,0.635) 8(2.725,1.905)
  silkscreen extent -3.3,-2.5 0.9,2.5, body extent -3,-2.45 3,2.45, height 1.63
DAP0032A_N [mm]
  rrect22% 1.4x0.45 smd: 1(-3.8,4.875) 2(-3.8,4.225) 3(-3.8,3.575) 4(-3.8,2.925) 5(-3.8,2.275) 6(-3.8,1.625) 7(-3.8,0.975) 8(-3.8,0.325) 9(-3.8,-0.325) 10(-3.8,-0.975) 11(-3.8,-1.625) 12(-3.8,-2.275) 13(-3.8,-2.925) 14(-3.8,-3.575) 15(-3.8,-4.225) 16(-3.8,-4.875) 17(3.8,-4.875) 18(3.8,-4.225) 19(3.8,-3.575) 20(3.8,-2.925) 21(3.8,-2.275) 22(3.8,-1.625) 23(3.8,-0.975) 24(3.8,-0.325) 25(3.8,0.325) 26(3.8,0.975) 27(3.8,1.625) 28(3.8,2.275) 29(3.8,2.925) 30(3.8,3.575) 31(3.8,4.225) 32(3.8,4.875)
  rrect2% 5.2x11 smd paste-2.6 mask-2.6: 33(0,0)
  rrect2% 4.11x4.36 on Top Paste: 33(0,0)
  rrect2% 4.11x4.36 on Top Solder: 33(0,0)
  silkscreen extent -4.45,-5.7 3.25,5.7, body extent -4.06,-5.5 4.06,5.5, height 1.2
DGQ0010D_N [mm] "TSSOP, 10-Leads, Body 3x3mm, Pitch 0.5mm, Thermal Pad 1.88x1.57mm, IPC Medium Density"
  rrect100% 1.35x0.3 smd: 1(-2.225,1) 2(-2.225,0.5) 3(-2.225,0) 4(-2.225,-0.5) 5(-2.225,-1) 6(2.225,-1) 7(2.225,-0.5) 8(2.225,0) 9(2.225,0.5) 10(2.225,1)
  rrect9% 2.2x3.1 smd paste-2 mask-2: 11(0,0)
  rrect5% 1.83x1.89 on Top Paste: 11(0,0)
  rrect5% 1.83x1.89 on Top Solder: 11(0,0)
  silkscreen extent -2.65,-1.55 0.9,1.55, body extent -2.46,-1.5 2.46,1.5, height 1.1
FCC_disclaimer [mil]
Fiducial10-20 [mm]
  round 1 smd mask+0.5: 1(0,0)
  Top Layer keep-out circle w1.178: c0,0 r0.5
FP-BSS123-7-F_SOT23-MFG [mm]
  rrect13% 0.9x0.8 smd paste+0 mask+0: 1(-1,0.95) 2(-1,-0.95) 3(1,0)
  body extent -1.2,-1.45 1.2,1.45, height 1.1
Keystone1502-2 [mm] "Double Turret"
  round 3.5 hole 2.5: 1(0,0)
  silkscreen extent -2.3,-2.3 2.3,2.3, body extent -1.6,-1.6 1.59,1.6, height 5.62
Keystone_1902C [mil] "Hex Standoff, 4-40 threaded, nylon"
  round 1 on Mech4: 0(0,0)
  body extent -145,-126 146,126, height 501
Label_650x200 [mil] "Thermal Transfer Label"
  round 1 on Mech13: 0(0,0)
  silkscreen extent -325,-100 325,100, body extent -325,-100 325,100, height 1
LG_R971_Green [mm] "SMD, 2-Leads, Body 2x1.25mm"
  rect 1.2x1.2 smd: 1(-1.05,0) 2(1.05,0)
  silkscreen extent -1.5,-1 2.4,1, body extent -1.05,-0.67 1.05,0.67, height 0.91
LPS3010 [mm] "Coilcraft recommended land pattern.  Document 428-2, rev 10/6/08"
  rect 0.63x3.3 smd: 1(-1.335,0) 2(1.335,0)
  rect 1.14x0.64 smd: 1(-1.08,-1.33) 1(-1.08,1.33) 2(1.08,-1.33) 2(1.08,1.33)
  silkscreen extent -2.59,-2 2,2, body extent -1.58,-1.58 1.58,1.58, height 1.02
MSD1278 [mil] "COILCRAFT"
  rect 157x79 smd mask+3: 1(-167.32,69) 2(-167.32,-69) 3(167.32,-69) 4(167.32,69)
  silkscreen extent -260,-245 245,245, body extent -240,-240 240,240, height 309
NDK_NX3225GA [mm] "NDK"
  rect 1.2x1.4 smd: 1(-0.8,1.1) 2(-0.8,-1.1) 3(0.8,-1.1) 4(0.8,1.1)
  silkscreen extent -1.9,-0.1 1.4,2, body extent -1.3,-1.65 1.3,1.65, height 0.9
"NY PMS 440 0025 PH" [mm] "4-40 nylon screw and mounting hole"
  round 6.35 hole 3.2: 1(0,0)
  body extent -3.3,-3.3 3.3,3.3, height 2.69
PDT0128A [mm] "Thin QFP, 128-Leads, Body 14x14mm, Pitch 0.4mm"
  oval 1.4x0.2 smd: 1(-7.7,6.2) 2(-7.7,5.8) 3(-7.7,5.4) 4(-7.7,5) 5(-7.7,4.6) 6(-7.7,4.2) 7(-7.7,3.8) 8(-7.7,3.4) 9(-7.7,3) 10(-7.7,2.6) 11(-7.7,2.2) 12(-7.7,1.8) 13(-7.7,1.4) 14(-7.7,1) 15(-7.7,0.6) 16(-7.7,0.2) 17(-7.7,-0.2) 18(-7.7,-0.6) 19(-7.7,-1) 20(-7.7,-1.4) 21(-7.7,-1.8) 22(-7.7,-2.2) 23(-7.7,-2.6) 24(-7.7,-3) 25(-7.7,-3.4) 26(-7.7,-3.8) 27(-7.7,-4.2) 28(-7.7,-4.6) 29(-7.7,-5) 30(-7.7,-5.4) 31(-7.7,-5.8) 32(-7.7,-6.2) 65(7.7,-6.2) 66(7.7,-5.8) 67(7.7,-5.4) 68(7.7,-5) 69(7.7,-4.6) 70(7.7,-4.2) 71(7.7,-3.8) 72(7.7,-3.4) 73(7.7,-3) 74(7.7,-2.6) 75(7.7,-2.2) 76(7.7,-1.8) 77(7.7,-1.4) 78(7.7,-1) 79(7.7,-0.6) 80(7.7,-0.2) 81(7.7,0.2) 82(7.7,0.6) 83(7.7,1) 84(7.7,1.4) 85(7.7,1.8) 86(7.7,2.2) 87(7.7,2.6) 88(7.7,3) 89(7.7,3.4) 90(7.7,3.8) 91(7.7,4.2) 92(7.7,4.6) 93(7.7,5) 94(7.7,5.4) 95(7.7,5.8) 96(7.7,6.2)
  oval 0.2x1.4 smd: 33(-6.2,-7.7) 34(-5.8,-7.7) 35(-5.4,-7.7) 36(-5,-7.7) 37(-4.6,-7.7) 38(-4.2,-7.7) 39(-3.8,-7.7) 40(-3.4,-7.7) 41(-3,-7.7) 42(-2.6,-7.7) 43(-2.2,-7.7) 44(-1.8,-7.7) 45(-1.4,-7.7) 46(-1,-7.7) 47(-0.6,-7.7) 48(-0.2,-7.7) 49(0.2,-7.7) 50(0.6,-7.7) 51(1,-7.7) 52(1.4,-7.7) 53(1.8,-7.7) 54(2.2,-7.7) 55(2.6,-7.7) 56(3,-7.7) 57(3.4,-7.7) 58(3.8,-7.7) 59(4.2,-7.7) 60(4.6,-7.7) 61(5,-7.7) 62(5.4,-7.7) 63(5.8,-7.7) 64(6.2,-7.7) 97(6.2,7.7) 98(5.8,7.7) 99(5.4,7.7) 100(5,7.7) 101(4.6,7.7) 102(4.2,7.7) 103(3.8,7.7) 104(3.4,7.7) 105(3,7.7) 106(2.6,7.7) 107(2.2,7.7) 108(1.8,7.7) 109(1.4,7.7) 110(1,7.7) 111(0.6,7.7) 112(0.2,7.7) 113(-0.2,7.7) 114(-0.6,7.7) 115(-1,7.7) 116(-1.4,7.7) 117(-1.8,7.7) 118(-2.2,7.7) 119(-2.6,7.7) 120(-3,7.7) 121(-3.4,7.7) 122(-3.8,7.7) 123(-4.2,7.7) 124(-4.6,7.7) 125(-5,7.7) 126(-5.4,7.7) 127(-5.8,7.7) 128(-6.2,7.7)
  silkscreen extent -7.7,-6.3 6.3,6.99, body extent -8,-8 8,8, height 1.07
POWERDI5 [mm] "Diodes Inc recommended land pattern, ap02001.pdf rev 60"
  rect 1.4x1.39 smd: 1(-1.991,0.92) 2(-1.991,-0.92)
  rect 4.86x3.36 smd: 3(1.991,0)
  silkscreen extent -1.7,-2.1 3.8,2.1, body extent -2.27,-2.02 4.33,2.03, height 1.17
PowerPAK_1212-8#1 [mm] "Vishay PowerPAK 1212-8, Body 3.4x3.2mm (max), Pitch 0.65mm, IPC Medium Density"
  rrect50% 0.73x0.4 smd paste-0.05 mask-0.05: 1(-1.535,0.991) 2(-1.535,0.33) 3(-1.535,-0.33) 4(-1.535,-0.991)
  rrect50% 0.71x0.4 smd paste-0.05 mask-0.05: 5(1.545,-0.991) 6(1.545,-0.33) 7(1.545,0.33) 8(1.545,0.991)
  rrect30% 0.33x0.6 on Bottom Paste: 9(-0.195,-1.55) 9(-0.195,1.55)
  rrect30% 0.33x3.7 on Bottom Solder: 9(-0.195,0)
  rrect11% 1.3x0.94 on Bottom Paste: 9(0.39,-0.57) 9(0.39,0.57)
  rrect6% 1.6x2.28 on Bottom Solder: 9(0.54,0)
  rrect9% 2.31x3.3 smd paste-2 mask-2: 9(0.745,0)
  Top Layer region: -0.41,-1.8 -0.41,1.8 -0.402,1.838 -0.381,1.871 -0.348,1.892 -0.31,1.9 -0.31,1.9 -0.08,1.9 -0.042,1.892 -0.009,1.871 0.012,1.838 0.02,1.8 0.02,1.8 0.02,-1.8 0.012,-1.838 -0.009,-1.871 -0.042,-1.892 -0.08,-1.9 -0.08,-1.9 -0.31,-1.9 -0.348,-1.892 -0.381,-1.871 -0.402,-1.838 -0.41,-1.8
  silkscreen extent -1.75,-1.75 1.75,1.75, body extent -1.65,-1.66 1.65,1.64, height 1.08
PowerPAK_1212-8#2 [mm] "Vishay PowerPAK 1212-8, Body 3.4x3.2mm (max), Pitch 0.65mm, IPC Medium Density"
  rrect50% 0.73x0.4 smd paste-0.05 mask-0.05: 1(-1.535,0.991) 2(-1.535,0.33) 3(-1.535,-0.33) 4(-1.535,-0.991)
  rrect50% 0.71x0.4 smd paste-0.05 mask-0.05: 5(1.545,-0.991) 6(1.545,-0.33) 7(1.545,0.33) 8(1.545,0.991)
  rrect30% 0.33x0.6 on Top Paste: 9(-0.195,1.55) 9(-0.195,-1.55)
  rrect30% 0.33x3.7 on Top Solder: 9(-0.195,0)
  rrect11% 1.3x0.94 on Top Paste: 9(0.39,0.57) 9(0.39,-0.57)
  rrect6% 1.6x2.28 on Top Solder: 9(0.54,0)
  rrect9% 2.31x3.3 smd paste-2 mask-2: 9(0.745,0)
  Top Layer region: -0.41,-1.8 -0.41,1.8 -0.402,1.838 -0.381,1.871 -0.348,1.892 -0.31,1.9 -0.31,1.9 -0.08,1.9 -0.042,1.892 -0.009,1.871 0.012,1.838 0.02,1.8 0.02,1.8 0.02,-1.8 0.012,-1.838 -0.009,-1.871 -0.042,-1.892 -0.08,-1.9 -0.08,-1.9 -0.31,-1.9 -0.348,-1.892 -0.381,-1.871 -0.402,-1.838 -0.41,-1.8
  silkscreen extent -1.75,-1.75 1.75,1.75, body extent -1.65,-1.66 1.65,1.64, height 1.08
PowerPAK_SO-8L [mm] "based on Vishay recommended land pattern Document 63818 Feb 7, 2012"
  rect 1x0.41 smd: 1(-2.805,1.905) 2(-2.805,0.635) 3(-2.805,-0.635) 4(-2.805,-1.905)
  rect 3.63x4.061 smd: 5(0.805,0)
  Top Layer region: 2.615,-2.5 3.125,-2.5 3.125,2.5 2.615,2.5
  Top Layer region: -0.298,2.03 0.297,2.03 0.297,2.64 -0.298,2.64
  Top Layer region: -0.297,-2.64 0.298,-2.64 0.298,-2.03 -0.297,-2.03
  body extent -3.07,-2.57 3.07,2.57, height 1.21
PWP0020A_N [mm] "TSOP, 20-Leads, Body 6.5x4.4mm, Pitch 0.65mm, Exposed Pad, IPC Medium Density"
  rrect22% 1.4x0.45 smd: 1(-2.95,2.925) 2(-2.95,2.275) 3(-2.95,1.625) 4(-2.95,0.975) 5(-2.95,0.325) 6(-2.95,-0.325) 7(-2.95,-0.975) 8(-2.95,-1.625) 9(-2.95,-2.275) 10(-2.95,-2.925) 11(2.95,-2.925) 12(2.95,-2.275) 13(2.95,-1.625) 14(2.95,-0.975) 15(2.95,-0.325) 16(2.95,0.325) 17(2.95,0.975) 18(2.95,1.625) 19(2.95,2.275) 20(2.95,2.925)
  rrect6% 3.4x6.5 smd paste-2 mask-2: 21(0,0)
  rrect3% 3.15x4.35 on Top Paste: 21(0,0)
  rrect3% 3.15x4.35 on Top Solder: 21(0,0)
  silkscreen extent -3.55,-3.3 1.5,3.4, body extent -3.21,-3.25 3.21,3.25, height 1
RHM0032C [mm] "VQFNP-32"
  rrect40% 0.6x0.25 smd: 1(-2.4,1.75) 2(-2.4,1.25) 3(-2.4,0.75) 4(-2.4,0.25) 5(-2.4,-0.25) 6(-2.4,-0.75) 7(-2.4,-1.25) 8(-2.4,-1.75) 17(2.4,-1.75) 18(2.4,-1.25) 19(2.4,-0.75) 20(2.4,-0.25) 21(2.4,0.25) 22(2.4,0.75) 23(2.4,1.25) 24(2.4,1.75)
  rrect40% 0.25x0.6 smd: 9(-1.75,-2.4) 10(-1.25,-2.4) 11(-0.75,-2.4) 12(-0.25,-2.4) 13(0.25,-2.4) 14(0.75,-2.4) 15(1.25,-2.4) 16(1.75,-2.4) 25(1.75,2.4) 26(1.25,2.4) 27(0.75,2.4) 28(0.25,2.4) 29(-0.25,2.4) 30(-0.75,2.4) 31(-1.25,2.4) 32(-1.75,2.4)
  rect 3.2x3.2 smd paste-2: 33(0,0)
  body extent -2.5,-2.5 2.5,2.5, height 0.85
Samtec_FTSH-105-01-x-DV [mm] "Header, 1.27mm, 5x2, SMT"
  rect 2.79x0.74 smd: 1(-2.035,2.54) 2(2.035,2.54) 3(-2.035,1.27) 4(2.035,1.27) 5(-2.035,0) 6(2.035,0) 7(-2.035,-1.27) 8(2.035,-1.27) 9(-2.035,-2.54) 10(2.035,-2.54)
  silkscreen extent -3.73,-3.48 3.73,3.48, body extent -2.92,-3.17 2.92,3.18, height 5.98
SM_RADIAL_D [mm] "6.3 x 5.8mm:  Panasonic D"
  rect 3.2x1.6 smd: 1(-2.5,0) 2(2.5,0)
  silkscreen extent -3.4,-3.4 3.4,3.4, body extent -3.4,-3.4 3.4,3.4, height 6.1
SM_RADIAL_F [mm] "8 x 10.2mm:  Panasonic F"
  rect 4x2 smd: 1(-3.55,0) 2(3.55,0)
  silkscreen extent -4.25,-4.25 4.25,4.25, body extent -4.25,-4.25 4.25,4.25, height 10.5
SMA [mm] "Molded Diode, 2-Leads, Body 4.3x2.6mm, IPC Medium Density, based on OnSemi component dimensions and land pattern"
  rect 2x2 smd: 1(-2,0) 2(2,0)
  silkscreen extent -3.66,-1.57 2.79,1.57, body extent -2.6,-1.3 2.6,1.3, height 2.42
SMA_Bi [mm] "SMD, 2-Leads, Body 4.275x2.575mm"
  rect 1.4x1.64 smd: 1(-2.015,0) 2(2.015,0)
  silkscreen extent -2.3,-1.45 2.3,1.45, body extent -2.52,-1.45 2.52,1.45, height 2.65
SMAF [mm] "SMD, 2-Leads, Body 3.8x2.5mm"
  rect 1.24x1.89 smd: 1(-2.04,0) 2(2.04,0)
  silkscreen extent -3.4,-1.3 2.8,1.3, body extent -2.35,-1.25 2.35,1.25, height 1
SOD-123 [mm] "On Semi recommended land pattern"
  rect 0.915x1.22 smd: 1(-1.637,0) 2(1.637,0)
  silkscreen extent -2.74,-1.17 2.03,1.17, body extent -1.93,-0.9 1.93,0.9, height 1.35
SOT-23 [mm] "SOT23, 3-Leads, Body 2.9x1.3mm, Pitch 0.95mm, Lead Span 2.5mm, IPC Medium Density"
  rrect50% 1x0.6 smd: 1(-1.2,0.95) 2(-1.2,-0.95) 3(1.2,0)
  silkscreen extent -1.63,-1.5 0.7,1.5, body extent -1.16,-1.45 1.21,1.45, height 1
SPM6545VT [mm] "TDK"
  rrect4% 2.3x3.3 smd: 1(-2.95,0) 2(2.95,0)
  body extent -3.5,-3.25 3.5,3.25, height 4.36
SPM12565VT [mm] "SMD, 2-Leads, Body 13x12.5mm"
  rrect3% 3.25x5 smd: 1(-5.725,0) 2(5.725,0)
  body extent -6.7,-6.45 6.7,6.45, height 6.5
Sullins_EDGE_CONN_EBC18DCWN-S371 [mm] "Edge Card Connector, 2.54mm, 18x2"
  rect 1.78x4.12 smd paste-1.016 mask+0: 1(-21.59,3.57) 3(-19.05,3.57) 5(-16.51,3.57) 7(-13.97,3.57) 9(-11.43,3.57) 11(-8.89,3.57) 13(-6.35,3.57) 15(-3.81,3.57) 17(-1.27,3.57) 19(1.27,3.57) 21(3.81,3.57) 23(6.35,3.57) 25(8.89,3.57) 27(11.43,3.57) 29(13.97,3.57) 31(16.51,3.57) 33(19.05,3.57) 35(21.59,3.57)
  rect 1.78x4.12 smd far side paste-1.016 mask+0: 2(-21.59,3.57) 4(-19.05,3.57) 6(-16.51,3.57) 8(-13.97,3.57) 10(-11.43,3.57) 12(-8.89,3.57) 14(-6.35,3.57) 16(-3.81,3.57) 18(-1.27,3.57) 20(1.27,3.57) 22(3.81,3.57) 24(6.35,3.57) 26(8.89,3.57) 28(11.43,3.57) 30(13.97,3.57) 32(16.51,3.57) 34(19.05,3.57) 36(21.59,3.57)
Testpoint_Keystone_Miniature [mil] "Miniature SMT test point"
  rect 135x70 smd: 1(0,0)
  silkscreen extent -78,-46 78,45, body extent -52,-20 52,20, height 61
TI_Stacked_Overlay_Small [mil]
  silkscreen extent -418,-98 418,98
WEEE_Minimum [mil] "WEEElie bin"
  silkscreen extent -95,-172 99,104
XAL4040 [mil] "Coilcraft XAL4040 7/18/12"
  rect 38x146 smd: 1(-46.5,0) 2(46.5,0)
  silkscreen extent -85,-85 85,85, body extent -84,-84 84,84, height 161
XAL6030 [mm] "Coilcraft recommended land pattern Document 887-4 Revised 01/14/18"
  rrect7% 1.43x5.5 smd: 1(-2.019,0) 2(2.019,0)
  body extent -3.28,-3.38 3.28,3.38, height 3.11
